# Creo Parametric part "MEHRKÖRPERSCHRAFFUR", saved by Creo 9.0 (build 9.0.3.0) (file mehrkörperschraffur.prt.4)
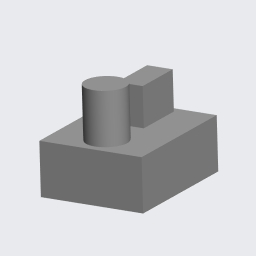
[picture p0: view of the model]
Materials in the file: S235JRG2

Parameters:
  BENENNUNG = "XXX"
  DATUM = "XX.XX.XX"
  ERSTELLER = "ARINDA"
  TEILETYP = "Fertigungsteil"
  PTC_MASTER_MATERIAL = "S235JRG2"
  SELECT_EN_NAME = "S235JRG2"
  SELECT_DIN_NAME = "RSt37-2"
  SELECT_DIN_NUMBER = "1.0038"
  SELECT_ASTM_NAME = "A 283 M Grade 2"
  MATERIAL_GROUP = "ME_ST_Baustahl"
  STANDARD_EN_DELIVERYSPEC = "DIN EN 10025"
  STANDARD_DIN_DELIVERYSPEC = "DIN 17100"

Other parameters: MASSE

Created from: ARINDA-STARTTEIL.PRT

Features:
  1. coordinate system "CS0"
  2. datum plane "DTM1", "T_RECHTS_Y-Z"
  3. datum plane "DTM2", "T_OBEN_X-Z"
  4. datum plane "DTM3", "T_VORNE_X-Y"
  5. datum axis "T_X-ACHSE"
  6. datum axis "A_1"
  7. datum axis "A_2"
  8. extrusion "Profil 1"
  9. extrusion "Profil 2"
  10. extrusion "Profil 1"

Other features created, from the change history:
  planar section "XSEC0001"

Other named items: T_BASIC, KÖRPER_1, KÖRPER_2, KÖRPER_3, T_Y-ACHSE, T_Z-ACHSE

Layers: 00_STD-ACHSEN, 00_STD-EBENEN, 00_STD-KOORDSYS, 01_ACHSEN, VOLUMENGEOMETRIE

Surfaces: 14 plane, 1 cylinder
